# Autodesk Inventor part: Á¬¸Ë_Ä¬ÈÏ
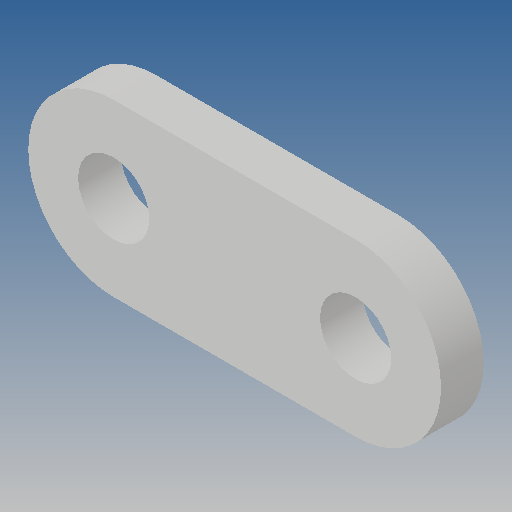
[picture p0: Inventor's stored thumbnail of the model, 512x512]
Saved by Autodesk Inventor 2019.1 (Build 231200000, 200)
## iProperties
Created: 2012-10
Part Number: Á¬¸Ë_Ä¬ÈÏ
Material: Ogólny
Document SubType Name: Modeling
Designer: CADENGINEERING4
Density: 1 g/cm^3
Appearance: Domyślna
Author: CADENGINEERING4
Revision Number: ÈÎºÎ
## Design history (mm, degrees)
feature "NONE"
node "Bryła1"
